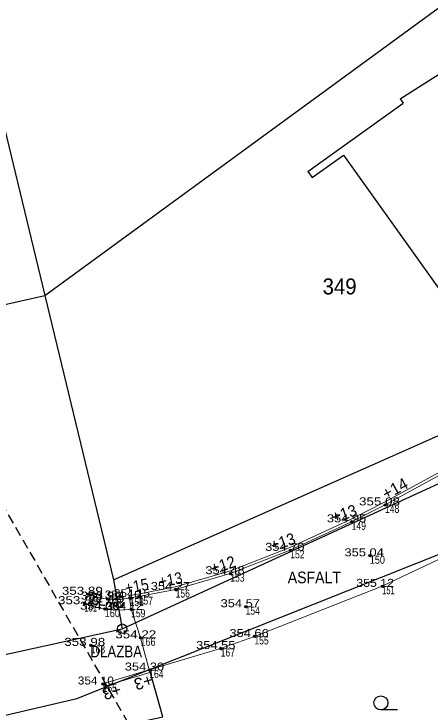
# Model space of a CAD drawing. Extents: x -592965 to -592390, y -1145071 to -1144631.
# Drawn here: x -592689.4 to -592667.32, y -1144937.57 to -1144900.54 of the extents above; entities that cross this region are included whole.
import ezdxf
from ezdxf.enums import TextEntityAlignment as Align

# ---------------------------------------------------------------- set-up
doc = ezdxf.new("R2010")
doc.units = 0
doc.header["$LTSCALE"] = 0.17
doc.header["$PDMODE"] = 32
doc.header["$PDSIZE"] = 0.085
doc.linetypes.add('MEDIUM_DASHED', pattern=[4.5, 3, -1.5])
for name, color, linetype, lineweight in [('1', 7, 'Continuous', 13), ('3', 7, 'Continuous', 13), ('4', 7, 'Continuous', 25)]:
    doc.layers.add(name, color=color, linetype=linetype, lineweight=lineweight)
doc.layers.add('2', color=7, linetype='Continuous')

msp = doc.modelspace()

# ---------------------------------------------------------------- linework, layer by layer
at = {"layer": '1'}
for p, q in [((-592683.26, -1144931.52), (-592683.28, -1144931.38)), ((-592684.69, -1144936.08), (-592682.22, -1144935.34))]:
    msp.add_line(p, q, dxfattribs=at)
for points in [[(-592652.64, -1144913.26), (-592654.61, -1144915.47), (-592656.66, -1144917.59), (-592657.4, -1144918.26), (-592661.22, -1144921.38), (-592662.03, -1144921.97), (-592663.69, -1144923.08), (-592665.53, -1144924.14), (-592669.78, -1144926.46), (-592671.54, -1144927.35), (-592674.79, -1144928.86), (-592677.96, -1144930.1), (-592680.85, -1144930.93), (-592682.8, -1144931.31), (-592683.28, -1144931.38)], [(-592682.22, -1144935.34), (-592678.43, -1144934.2), (-592676.64, -1144933.56), (-592669.86, -1144930.9), (-592663.54, -1144927.9), (-592658.53, -1144924.2), (-592654.07, -1144920.31), (-592649.9, -1144915.93), (-592646.93, -1144913.3), (-592646.77, -1144913.16)], [(-592656.56, -1144917.69), (-592657.31, -1144918.37), (-592661.13, -1144921.49), (-592661.95, -1144922.08), (-592663.62, -1144923.2), (-592665.46, -1144924.26), (-592669.71, -1144926.58), (-592671.48, -1144927.48), (-592674.74, -1144928.99), (-592677.92, -1144930.23), (-592680.82, -1144931.07), (-592682.78, -1144931.45), (-592683.26, -1144931.52)], [(-592682.22, -1144935.34), (-592682.69, -1144933.63), (-592683.18, -1144932.12), (-592683.26, -1144931.52)], [(-592684.65, -1144936.21), (-592682.18, -1144935.47), (-592682.22, -1144935.34)]]:
    msp.add_lwpolyline(points, dxfattribs=at)
for centre, radius, start, end in [((-592684.0349, -1144927.9145), 3.6879, 247.43517, 282.12879), ((-592683.845, -1144927.2168), 4.9481, 248.48139, 277.72376)]:
    msp.add_arc(centre, radius, start, end, dxfattribs=at)
at = {"layer": '2'}
for p in [(-592669.71, -1144926.58), (-592671.48, -1144927.48), (-592674.74, -1144928.99), (-592670.52, -1144929.28), (-592677.92, -1144930.23), (-592669.86, -1144930.9), (-592685.45, -1144931.32), (-592680.82, -1144931.07), (-592684.44, -1144931.58), (-592683.26, -1144931.52), (-592682.78, -1144931.45), (-592685.66, -1144931.82), (-592677.11, -1144931.98), (-592684.58, -1144932.11), (-592683.18, -1144932.12), (-592682.69, -1144933.63), (-592676.64, -1144933.56), (-592685.32, -1144934.03), (-592678.43, -1144934.2), (-592682.22, -1144935.34), (-592684.69, -1144936.08)]:
    msp.add_point(p, dxfattribs=at)
at = {"layer": '3'}
for centre, radius in [((-592669.7101, -1144926.5799), 0.0625), ((-592669.7101, -1144926.5799), 0.0395), ((-592669.7101, -1144926.5799), 0.0125), ((-592671.4801, -1144927.4799), 0.0625), ((-592671.4801, -1144927.4799), 0.0395), ((-592671.4801, -1144927.4799), 0.0125), ((-592674.7401, -1144928.9899), 0.0625), ((-592674.7401, -1144928.9899), 0.0395), ((-592674.7401, -1144928.9899), 0.0125), ((-592670.5201, -1144929.2799), 0.0625), ((-592670.5201, -1144929.2799), 0.0395), ((-592670.5201, -1144929.2799), 0.0125), ((-592677.9201, -1144930.2299), 0.0625), ((-592677.9201, -1144930.2299), 0.0395), ((-592677.9201, -1144930.2299), 0.0125), ((-592669.8601, -1144930.8999), 0.0625), ((-592669.8601, -1144930.8999), 0.0395), ((-592669.8601, -1144930.8999), 0.0125), ((-592685.4501, -1144931.3199), 0.0625), ((-592685.4501, -1144931.3199), 0.0395), ((-592680.8201, -1144931.0699), 0.0625), ((-592680.8201, -1144931.0699), 0.0395), ((-592680.8201, -1144931.0699), 0.0125), ((-592685.4501, -1144931.3199), 0.0125), ((-592684.4401, -1144931.5799), 0.0625), ((-592684.4401, -1144931.5799), 0.0395), ((-592684.4401, -1144931.5799), 0.0125), ((-592683.2601, -1144931.5199), 0.0625), ((-592683.2601, -1144931.5199), 0.0395), ((-592683.2601, -1144931.5199), 0.0125), ((-592682.7801, -1144931.4499), 0.0625), ((-592682.7801, -1144931.4499), 0.0395), ((-592682.7801, -1144931.4499), 0.0125), ((-592685.6601, -1144931.8199), 0.0625), ((-592685.6601, -1144931.8199), 0.0395), ((-592685.6601, -1144931.8199), 0.0125), ((-592677.1101, -1144931.9799), 0.0625), ((-592677.1101, -1144931.9799), 0.0395), ((-592677.1101, -1144931.9799), 0.0125), ((-592684.5801, -1144932.1099), 0.0625), ((-592684.5801, -1144932.1099), 0.0395), ((-592684.5801, -1144932.1099), 0.0125), ((-592683.1801, -1144932.1199), 0.0625), ((-592683.1801, -1144932.1199), 0.0395), ((-592683.1801, -1144932.1199), 0.0125), ((-592676.6401, -1144933.5599), 0.0625), ((-592682.6901, -1144933.6299), 0.0625), ((-592682.6901, -1144933.6299), 0.0395), ((-592682.6901, -1144933.6299), 0.0125), ((-592676.6401, -1144933.5599), 0.0395), ((-592676.6401, -1144933.5599), 0.0125), ((-592685.3201, -1144934.0299), 0.0625), ((-592685.3201, -1144934.0299), 0.0395), ((-592685.3201, -1144934.0299), 0.0125), ((-592678.4301, -1144934.1999), 0.0625), ((-592678.4301, -1144934.1999), 0.0395), ((-592678.4301, -1144934.1999), 0.0125), ((-592682.2201, -1144935.3399), 0.0625), ((-592682.2201, -1144935.3399), 0.0395), ((-592682.2201, -1144935.3399), 0.0125), ((-592684.6901, -1144936.0799), 0.0625), ((-592684.6901, -1144936.0799), 0.0395), ((-592684.6901, -1144936.0799), 0.0125)]:
    msp.add_circle(centre, radius, dxfattribs=at)
at = {"layer": '4'}
for p, q in [((-592687.76, -1144915.48), (-592649.48, -1144887.5)), ((-592668.9, -1144905.05), (-592662.52, -1144900.94)), ((-592690.94, -1144902.31), (-592687.76, -1144915.48)), ((-592673.81, -1144908.89), (-592668.74, -1144905.28)), ((-592668.9, -1144905.05), (-592668.74, -1144905.28)), ((-592673.58, -1144909.22), (-592671.91, -1144908.03)), ((-592671.91, -1144908.03), (-592666.22, -1144916.02)), ((-592673.81, -1144908.89), (-592673.58, -1144909.22)), ((-592710.37, -1144920.57), (-592687.76, -1144915.48)), ((-592687.76, -1144915.48), (-592684.12, -1144930.55)), ((-592683.65, -1144933.15), (-592650.24, -1144917.82)), ((-592684.12, -1144930.55), (-592656.42, -1144918.25)), ((-592682.2, -1144935.31), (-592657.03, -1144925.29)), ((-592684.12, -1144930.55), (-592683.65, -1144933.15)), ((-592695.37, -1144935.73), (-592683.65, -1144933.15)), ((-592669.055, -1144937.46), (-592669.93, -1144937.46))]:
    msp.add_line(p, q, dxfattribs=at)
at = {"layer": '4', "linetype": 'MEDIUM_DASHED'}
msp.add_lwpolyline([(-592857.7, -1144647.96), (-592827.25, -1144698.04), (-592798.73, -1144745.3), (-592765.1, -1144800.74), (-592721.92, -1144873.86), (-592693.51, -1144920.47), (-592669.72, -1144961.82), (-592709.34, -1144973.09), (-592761.29, -1144989.89), (-592825.83, -1145034.08), (-592878.88, -1145071.17)], dxfattribs=at)
at = {"layer": '4'}
for points in [[(-592709.85, -1144942.41), (-592686.06, -1144936.85), (-592682.2, -1144935.31)], [(-592709.5, -1144943.92), (-592681.5, -1144937.82), (-592682.2, -1144935.31)]]:
    msp.add_lwpolyline(points, dxfattribs=at)
for centre, radius in [((-592683.65, -1144933.15), 0.25), ((-592683.65, -1144933.15), 0.0164), ((-592669.93, -1144937.085), 0.375)]:
    msp.add_circle(centre, radius, dxfattribs=at)

# ---------------------------------------------------------------- texts
at = {"layer": '1'}
msp.add_text('+14', height=0.62, rotation=28.629, dxfattribs=at).set_placement((-592669.033, -1144925.9912), align=Align.CENTER)
for s, rotation, width, p in [('+13', 18.435, 0.95, (-592671.7735, -1144927.3415)), ('+13', 18.435, 0.95, (-592675.0335, -1144928.8415)), ('+12', 18.435, 0.95, (-592678.2035, -1144930.0615)), ('+13', 10.856, 0.9, (-592681.0324, -1144930.8532)), ('+15', 10.856, 0.9, (-592682.8224, -1144931.1932)), ('ZLAB', 352.439, 0.9, (-592684.4893, -1144931.9631)), ('+3', 196.678, 1.05, (-592682.6085, -1144935.6903)), ('+3', 196.678, 1.05, (-592684.2885, -1144936.2103))]:
    msp.add_text(s, height=0.62, rotation=rotation, dxfattribs=dict(at, width=width)).set_placement(p, align=Align.CENTER)
for s, width, p in [('ASFALT', 0.9, (-592673.46, -1144930.74)), ('DLAZBA', 0.85, (-592683.97, -1144934.67))]:
    msp.add_text(s, height=0.62, dxfattribs=dict(at, width=width)).set_placement(p, align=Align.CENTER)
at = {"layer": '2'}
for s, width, p in [('148', 0.8, (-592669.71, -1144927.005)), ('149', 0.8, (-592671.48, -1144927.905)), ('152', 0.8, (-592674.74, -1144929.415)), ('150', 0.85, (-592670.52, -1144929.705)), ('153', 0.8, (-592677.92, -1144930.655)), ('151', 0.7, (-592669.86, -1144931.325)), ('156', 0.8, (-592680.82, -1144931.495)), ('162', 0.8, (-592685.45, -1144931.745)), ('163', 0.8, (-592684.44, -1144932.005)), ('158', 0.8, (-592683.26, -1144931.945)), ('157', 0.8, (-592682.78, -1144931.875)), ('161', 0.7, (-592685.66, -1144932.245)), ('154', 0.8, (-592677.11, -1144932.405)), ('160', 0.85, (-592684.58, -1144932.535)), ('159', 0.8, (-592683.18, -1144932.545)), ('166', 0.85, (-592682.69, -1144934.055)), ('155', 0.8, (-592676.64, -1144933.985)), ('168', 0.8, (-592685.32, -1144934.455)), ('167', 0.8, (-592678.43, -1144934.625)), ('164', 0.8, (-592682.22, -1144935.765)), ('165', 0.8, (-592684.69, -1144936.505))]:
    msp.add_text(s, height=0.425, dxfattribs=dict(at, width=width)).set_placement(p)
at = {"layer": '3'}
for s, width, p in [('355 08', 1.25, (-592670.0025, -1144926.61)), ('354 95', 1.2, (-592671.75, -1144927.51)), ('354 70', 1.2, (-592675.025, -1144929.02)), ('355 04', 1.2, (-592670.8175, -1144929.31)), ('354 48', 1.2, (-592678.197, -1144930.26)), ('355 12', 1.15, (-592670.233, -1144930.93)), ('353 89', 1.25, (-592685.7685, -1144931.35)), ('354 27', 1.2, (-592681.0935, -1144931.1)), ('353 99', 1.25, (-592684.7655, -1144931.61)), ('354 10', 1.1, (-592683.622, -1144931.55)), ('354 15', 1.1, (-592683.137, -1144931.48)), ('353 88', 1.25, (-592685.9735, -1144931.85)), ('354 57', 1.2, (-592677.39, -1144932.01)), ('354 00', 1.2, (-592684.8485, -1144932.14)), ('354 12', 1.1, (-592683.5305, -1144932.15)), ('354 22', 1.25, (-592682.935, -1144933.66)), ('354 66', 1.2, (-592676.922, -1144933.59)), ('353 98', 1.25, (-592685.64, -1144934.06)), ('354 55', 1.2, (-592678.6885, -1144934.23)), ('354 30', 1.2, (-592682.4735, -1144935.37)), ('354 10', 1.1, (-592685.052, -1144936.11))]:
    msp.add_text(s, height=0.425, dxfattribs=dict(at, width=width)).set_placement(p, align=Align.CENTER)
at = {"layer": '4', "width": 0.95}
msp.add_text('349', height=0.85, dxfattribs=at).set_placement((-592673.02, -1144915.42))

doc.saveas('drawing.dxf')
